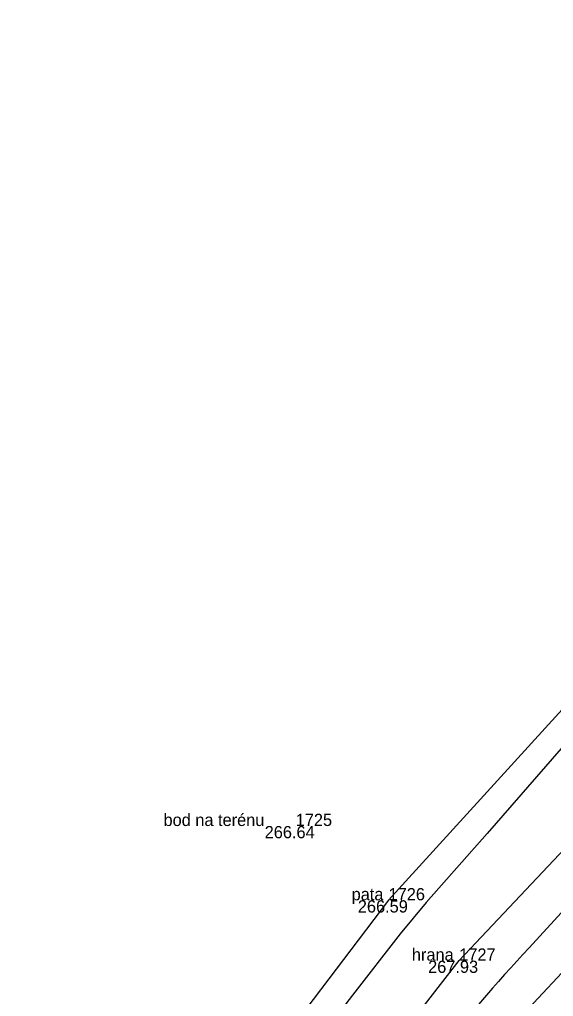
# Model space of a CAD drawing. Extents: x -567962 to -566460, y -1093720 to -1089838.
# Drawn here: x -566935.26 to -566913.41, y -1090226.7 to -1090186.72 of the extents above; entities that cross this region are included whole.
import ezdxf

# ---------------------------------------------------------------- set-up
doc = ezdxf.new("R2010")
doc.units = 0
for name, color, linetype in [('0_osa hráze', 7, 'Continuous'), ('bod_znacka', 7, 'Continuous'), ('cislo_bodu', 7, 'Continuous'), ('hrana_L', 7, 'Continuous'), ('kod_bodu', 7, 'Continuous'), ('norm_vrst', 7, 'Continuous'), ('vyska_bodu', 7, 'Continuous')]:
    doc.layers.add(name, color=color, linetype=linetype)

msp = doc.modelspace()

# ---------------------------------------------------------------- linework, layer by layer
at = {"layer": '0_osa hráze'}
msp.add_lwpolyline([(-566876.582, -1090186.718), (-566901.274, -1090210.335), (-566914.414, -1090224.7)], dxfattribs=at)
msp.add_arc((-566843.631, -1090289.76), 96.141, 137.41218, 144.50722, dxfattribs=at)
at = {"layer": 'bod_znacka'}
for p, q in [((-566923.96, -1090219.72), (-566923.96, -1090219.72)), ((-566920.16, -1090222.76), (-566920.16, -1090222.76)), ((-566917.27, -1090225.23), (-566917.27, -1090225.23))]:
    msp.add_line(p, q, dxfattribs=at)
at = {"layer": 'hrana_L'}
for p, q in [((-566920.16, -1090222.76), (-566896.97, -1090197.25)), ((-566894.09, -1090200.56), (-566917.27, -1090225.23)), ((-566892.08, -1090203.15), (-566914.61, -1090227.38)), ((-566920.16, -1090222.76), (-566935.26, -1090242.58)), ((-566932.7, -1090244.91), (-566917.27, -1090225.23))]:
    msp.add_line(p, q, dxfattribs=at)
at = {"layer": 'norm_vrst'}
msp.add_lwpolyline([(-566911.08, -1090214.232), (-566916.13, -1090220.032), (-566918.625, -1090222.853), (-566919.689, -1090224.127), (-566921.631, -1090226.636), (-566927.374, -1090234.13)], dxfattribs=at)

# ---------------------------------------------------------------- texts
at = {"layer": 'cislo_bodu'}
for s, p in [('1725', (-566923.96, -1090219.72)), ('1726', (-566920.16, -1090222.76)), ('1727', (-566917.27, -1090225.23))]:
    msp.add_text(s, height=0.5, dxfattribs=at).set_placement(p)
at = {"layer": 'kod_bodu'}
for s, p in [('bod na terénu', (-566929.369, -1090219.72)), ('pata', (-566921.672, -1090222.76)), ('hrana', (-566919.207, -1090225.23))]:
    msp.add_text(s, height=0.5, dxfattribs=at).set_placement(p)
at = {"layer": 'vyska_bodu'}
for s, p in [('266.64', (-566925.23, -1090220.22)), ('266.59', (-566921.418, -1090223.26)), ('267.93', (-566918.542, -1090225.73))]:
    msp.add_text(s, height=0.5, dxfattribs=at).set_placement(p)

doc.saveas('drawing.dxf')
